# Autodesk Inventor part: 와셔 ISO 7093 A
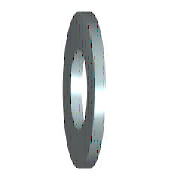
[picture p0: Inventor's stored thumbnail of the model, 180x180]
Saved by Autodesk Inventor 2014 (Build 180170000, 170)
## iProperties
Created: 2012-02
Part Number: 와셔 ISO 7093 A
Material: 스테인리스강
Description: 평면 와셔 - 대형 시리즈 - 제품 등급 A
Document SubType Name: Modeling
Standard: ISO 7093 A
Designer: mduedu
Standard Revision: First Edition 2000-06-01
Standards Organization: ISO
Language: ko-KR
Size Designation: ST 4 - 140 HV - A
Categories: <MemberInstance><Categories><Category DisplayName="조임쇠" InternalName="e4da775c-781d-43d5-af7c-5136215cf5a6" Mnemonic="FSTN"><Category DisplayName="와셔" InternalN
Density: 8.08 g/cm^3
Appearance: 파란색 - 벽 페인트 - 광택
Mass: 0.796489 g
Surface Area: 2.48359 cm^2
Volume: 0.0985753 cm^3
IsCustomPart: 1
Author: mduedu
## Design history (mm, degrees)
sketch "스케치"
  geometry: C1 r 6 at (0, 0); C2 r 2.15 at (0, 0); 1 further point
  constraints: 2 centre point, 2 coincident
  dimensions: "d0" = 4.3 diameter of C2 (= SD1); "d1" = 12 diameter of C1 (= SD2)
extrude "본체" new body sketch "스케치" distance "d2" = 1 (= SD); taper "d3" = 0 deg
workaxis "Work Axis1"
workplane "Work Plane1"
body "Solid1"
other parameters: "SD1" = 4.3 [user parameter; used in 1 equation term], "SD2" = 12 [user parameter; used in 1 equation term], "SD" = 1 [user parameter; used in 1 equation term], "d4" = 0, "d5" = 0, "d6" = 0, "d7" = 0, "NND" = 4 [user parameter]
